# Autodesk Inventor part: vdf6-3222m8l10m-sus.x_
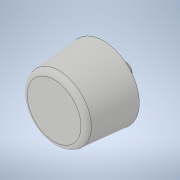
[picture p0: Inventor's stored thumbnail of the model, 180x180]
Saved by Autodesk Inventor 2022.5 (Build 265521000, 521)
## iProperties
Created: 2021-08
Part Number: vdf6-3222m8l10m-sus.x_
Material: 一般
Document SubType Name: Modeling
Designer: ImaoCorp
Density: 1 g/cm^3
Appearance: 既定
Sending System: SOLIDWORKS 2019-2019304
MC: AMD64
MC_MODEL: Intel64 Family 6 Model 60 Stepping 3, GenuineIntel
OS: Windows_NT
FRU: Parasolid Version 31.0, build 290,  9- 1-2019
FORMAT: text
GUISE: transmit
KEY: vdf6-3222m8l10m-sus
FILE: vdf6-3222m8l10m-sus.x_t
DATE: Wed Aug 11 14:59:02 2021
Author: ImaoCorp
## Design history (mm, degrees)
feature "Base1"
node "ソリッド1"
